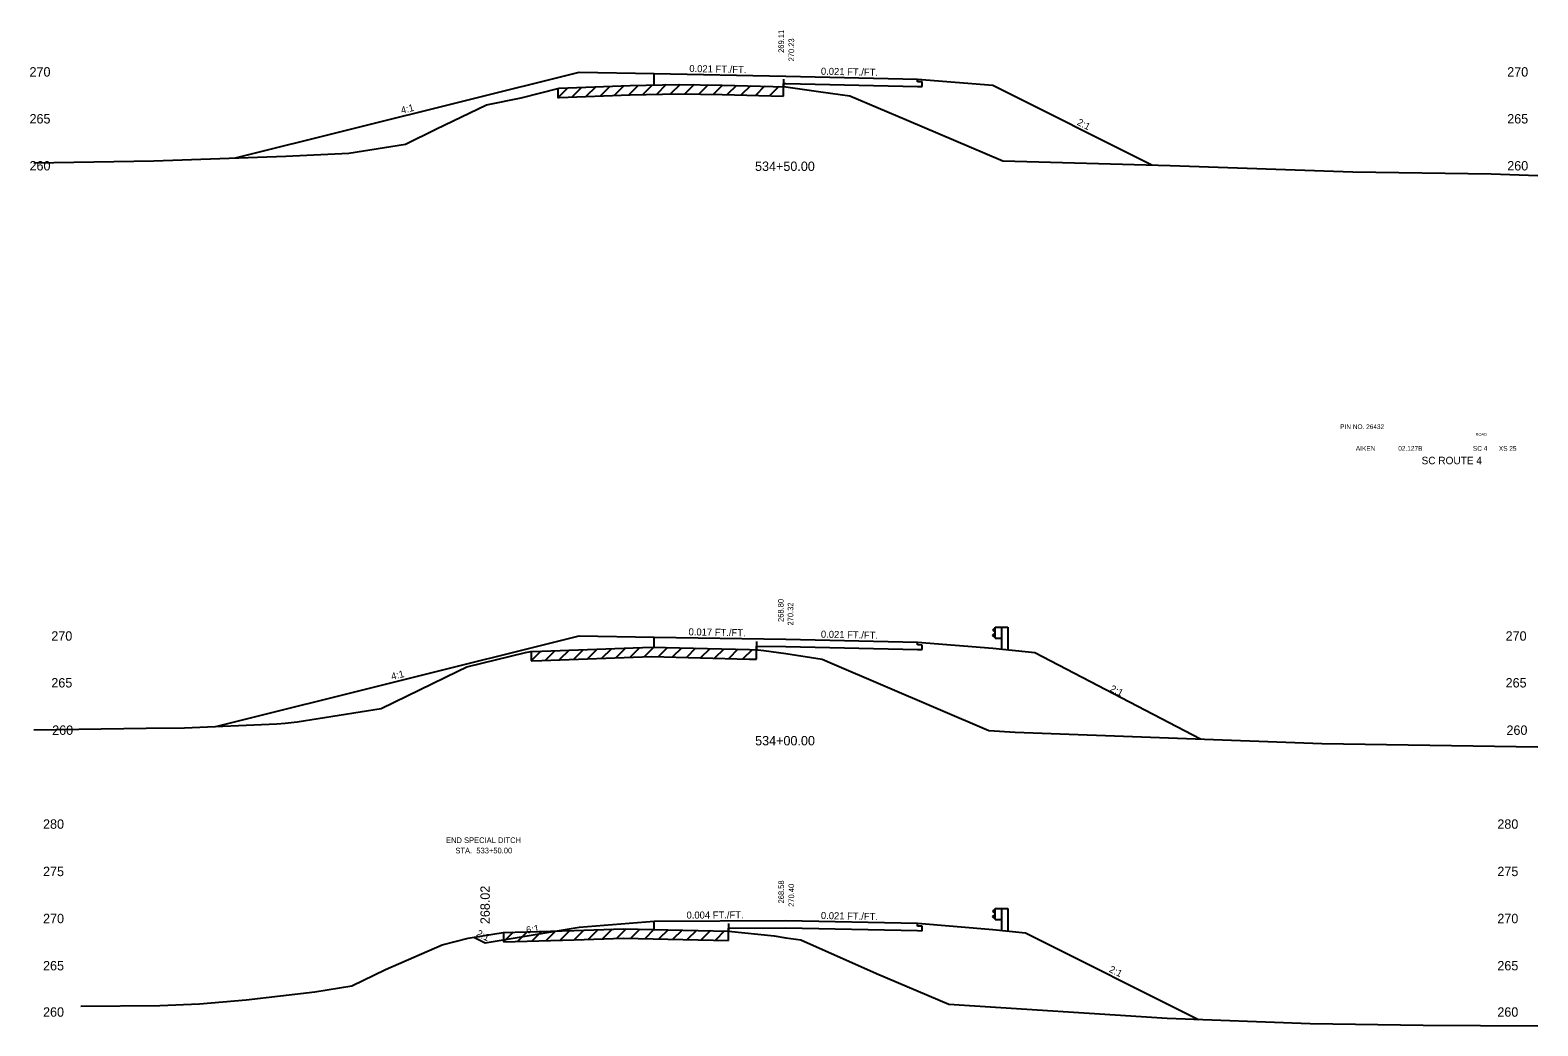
# Model space of a CAD drawing. Extents: x 883 to 1160, y 1002 to 4323.
# Drawn here: x 999.6 to 1160, y 3799.2 to 3905.1 of the extents above; entities that cross this region are included whole.
import ezdxf

# ---------------------------------------------------------------- set-up
doc = ezdxf.new("R2010")
doc.units = 0
for name, color, linetype in [('Level 1', 7, 'Continuous'), ('Level 10', 7, 'Continuous'), ('Level 11', 7, 'Continuous'), ('Level 12', 7, 'Continuous'), ('Level 24', 7, 'Continuous'), ('Level 3', 7, 'Continuous'), ('Level 32', 7, 'Continuous'), ('Level 33', 7, 'Continuous'), ('Level 53', 7, 'Continuous'), ('Level 59', 7, 'Continuous'), ('Level 6', 7, 'Continuous'), ('Level 60', 7, 'Continuous'), ('Level 61', 7, 'Continuous'), ('Level 7', 7, 'Continuous')]:
    doc.layers.add(name, color=color, linetype=linetype)

msp = doc.modelspace()

# ---------------------------------------------------------------- linework, layer by layer
at = {"layer": 'Level 11'}
for p, q in [((1066, 3899.3), (1066, 3900.52)), ((1094, 3899.64), (1094, 3899.94)), ((1094.5, 3899.63), (1094, 3899.64)), ((1094.5, 3899.15), (1094.5, 3899.63)), ((1094, 3899.16), (1094.5, 3899.15)), ((1066, 3839.47), (1066, 3840.57)), ((1094, 3839.73), (1094, 3840.03)), ((1094.5, 3839.72), (1094, 3839.73)), ((1094, 3839.25), (1094.5, 3839.24)), ((1094.5, 3839.24), (1094.5, 3839.72)), ((1066, 3809.45), (1066, 3810.35)), ((1094, 3809.81), (1094, 3810.11)), ((1094.5, 3809.8), (1094, 3809.81)), ((1094.5, 3809.32), (1094.5, 3809.8)), ((1094, 3809.33), (1094.5, 3809.32))]:
    msp.add_line(p, q, dxfattribs=at)
at = {"layer": 'Level 12'}
for p, q in [((1079.73, 3899.12), (1079.73, 3899.45)), ((1079.73, 3899.45), (1080, 3899.45)), ((1080, 3899.45), (1094, 3899.16)), ((1076.86, 3839.22), (1076.86, 3839.6)), ((1076.86, 3839.6), (1080, 3839.55)), ((1080, 3839.55), (1094, 3839.25)), ((1073.91, 3809.6), (1080, 3809.62)), ((1073.91, 3809.29), (1073.91, 3809.6)), ((1080, 3809.62), (1094, 3809.33))]:
    msp.add_line(p, q, dxfattribs=at)
at = {"layer": 'Level 24'}
for p, q in [((1102.27, 3840.45), (1102.27, 3841.62)), ((1102.27, 3841.62), (1102.94, 3841.62)), ((1102.94, 3841.62), (1102.94, 3839.27)), ((1102.94, 3841.62), (1103.6, 3841.62)), ((1103.6, 3841.62), (1103.6, 3839.21)), ((1102.27, 3841.54), (1102, 3841.34)), ((1102, 3841.34), (1102, 3841.29)), ((1102, 3841.29), (1102.27, 3841.09)), ((1102, 3840.77), (1102.27, 3840.97)), ((1102, 3840.72), (1102, 3840.77)), ((1102.27, 3840.52), (1102, 3840.72)), ((1102.27, 3840.45), (1102.94, 3840.45)), ((1102.27, 3811.62), (1102, 3811.42)), ((1102, 3811.42), (1102, 3811.37)), ((1102, 3811.37), (1102.27, 3811.17)), ((1102.27, 3810.53), (1102.27, 3811.69)), ((1102.27, 3811.69), (1102.94, 3811.69)), ((1102.94, 3811.69), (1102.94, 3809.35)), ((1102.94, 3811.69), (1103.6, 3811.69)), ((1103.6, 3811.69), (1103.6, 3809.28)), ((1102, 3810.85), (1102.27, 3811.05)), ((1102, 3810.8), (1102, 3810.85)), ((1102.27, 3810.6), (1102, 3810.8)), ((1102.27, 3810.53), (1102.94, 3810.53))]:
    msp.add_line(p, q, dxfattribs=at)
at = {"layer": 'Level 53'}
for p, q in [((1079.73, 3899.93), (1079.73, 3899.12)), ((1076.86, 3840.08), (1076.86, 3839.22)), ((1073.91, 3810.08), (1073.91, 3809.29))]:
    msp.add_line(p, q, dxfattribs=at)
at = {"layer": 'Level 59'}
for p, q in [((1066, 3900.52), (1080, 3900.23)), ((1080, 3900.23), (1094, 3899.94)), ((1066, 3840.57), (1080, 3840.33)), ((1080, 3840.33), (1094, 3840.03)), ((1066, 3810.35), (1080, 3810.4)), ((1080, 3810.4), (1094, 3810.11))]:
    msp.add_line(p, q, dxfattribs=at)
at = {"layer": 'Level 6'}
for p, q in [((1058, 3900.68), (1066, 3900.52)), ((1094, 3899.94), (1102, 3899.27)), ((1058, 3840.71), (1066, 3840.57)), ((1094, 3840.03), (1102, 3839.37)), ((1102, 3839.37), (1106.5, 3838.92)), ((1058, 3809.69), (1066, 3810.35)), ((1094, 3810.11), (1102, 3809.44)), ((1102, 3809.44), (1105.5, 3809.09))]:
    msp.add_line(p, q, dxfattribs=at)
at = {"layer": 'Level 60'}
for p, q in [((1063.42, 3899.24), (1068.59, 3899.37)), ((1068.59, 3899.37), (1073.21, 3899.3)), ((1048.14, 3897.21), (1051.82, 3897.95)), ((1051.82, 3897.95), (1055.88, 3898.96)), ((1055.88, 3898.96), (1063.42, 3899.24)), ((1073.21, 3899.3), (1080, 3899.11)), ((1080, 3899.11), (1083.71, 3898.57)), ((1083.71, 3898.57), (1086.8, 3898.15)), ((1086.8, 3898.15), (1092.82, 3895.61)), ((1042.77, 3894.59), (1048.14, 3897.21)), ((1039.54, 3893.01), (1042.77, 3894.59)), ((1092.82, 3895.61), (1103.09, 3891.22)), ((1033.51, 3892.05), (1039.54, 3893.01)), ((1012.74, 3891.22), (1026.81, 3891.74)), ((1026.81, 3891.74), (1033.51, 3892.05)), ((1000, 3891.03), (1012.74, 3891.22)), ((1103.09, 3891.22), (1120.87, 3890.75)), ((1120.87, 3890.75), (1140.33, 3890.05)), ((1140.33, 3890.05), (1155.03, 3889.84)), ((1155.03, 3889.84), (1160, 3889.69)), ((1046.07, 3837.38), (1052.3, 3838.94)), ((1052.3, 3838.94), (1052.87, 3839.03)), ((1052.87, 3839.03), (1054.03, 3839.06)), ((1054.03, 3839.06), (1065.69, 3839.48)), ((1065.69, 3839.48), (1076.14, 3839.23)), ((1076.14, 3839.23), (1077.01, 3839.21)), ((1077.01, 3839.21), (1077.66, 3839.14)), ((1077.66, 3839.14), (1080, 3838.8)), ((1080, 3838.8), (1083.86, 3838.23)), ((1036.96, 3832.98), (1045.11, 3836.95)), ((1045.11, 3836.95), (1046.07, 3837.38)), ((1083.86, 3838.23), (1084.91, 3837.76)), ((1084.91, 3837.76), (1101.6, 3830.63)), ((1028, 3831.56), (1036.96, 3832.98)), ((1000, 3830.71), (1011.95, 3830.87)), ((1011.95, 3830.87), (1016.03, 3830.89)), ((1016.03, 3830.89), (1025.86, 3831.33)), ((1025.86, 3831.33), (1026.73, 3831.41)), ((1026.73, 3831.41), (1028, 3831.56)), ((1101.6, 3830.63), (1104.38, 3830.45)), ((1104.38, 3830.45), (1137.02, 3829.23)), ((1137.02, 3829.23), (1160, 3828.89)), ((1057.46, 3809.34), (1062.72, 3809.53)), ((1062.72, 3809.53), (1067.44, 3809.42)), ((1043.44, 3807.83), (1046.2, 3808.53)), ((1046.2, 3808.53), (1049.94, 3809.12)), ((1049.94, 3809.12), (1057.46, 3809.34)), ((1067.44, 3809.42), (1073.89, 3809.29)), ((1073.89, 3809.29), (1078.77, 3808.76)), ((1078.77, 3808.76), (1080, 3808.58)), ((1080, 3808.58), (1081.6, 3808.34)), ((1081.6, 3808.34), (1089.65, 3804.78)), ((1037.4, 3805.18), (1043.44, 3807.83)), ((1033.82, 3803.44), (1037.4, 3805.18)), ((1089.65, 3804.78), (1097.33, 3801.5)), ((1029.9, 3802.82), (1033.82, 3803.44)), ((1013.41, 3801.35), (1017.62, 3801.54)), ((1017.62, 3801.54), (1022.58, 3801.97)), ((1022.58, 3801.97), (1029.9, 3802.82)), ((1097.33, 3801.5), (1120.55, 3800.02)), ((1005, 3801.31), (1013.41, 3801.35)), ((1120.55, 3800.02), (1135.77, 3799.45)), ((1135.77, 3799.45), (1147.79, 3799.27)), ((1147.79, 3799.27), (1160, 3799.2))]:
    msp.add_line(p, q, dxfattribs=at)
at = {"layer": 'Level 61'}
for p, q in [((1068.77, 3899.37), (1067.74, 3898.35)), ((1070.23, 3899.35), (1069.25, 3898.36)), ((1056.8, 3899), (1055.73, 3897.93)), ((1055.73, 3898.93), (1055.73, 3897.93)), ((1055.73, 3897.93), (1055.88, 3897.96)), ((1055.88, 3897.96), (1063.42, 3898.24)), ((1058.27, 3899.05), (1057.23, 3898.01)), ((1059.77, 3899.1), (1058.73, 3898.07)), ((1061.27, 3899.16), (1060.23, 3898.12)), ((1062.77, 3899.21), (1061.74, 3898.18)), ((1064.27, 3899.26), (1063.24, 3898.23)), ((1063.42, 3898.24), (1068.59, 3898.37)), ((1065.77, 3899.3), (1064.74, 3898.27)), ((1067.27, 3899.34), (1066.24, 3898.31)), ((1068.59, 3898.37), (1073.21, 3898.3)), ((1071.73, 3899.32), (1070.75, 3898.34)), ((1073.24, 3899.29), (1072.25, 3898.31)), ((1073.21, 3898.3), (1079.73, 3898.12)), ((1074.73, 3899.25), (1073.75, 3898.28)), ((1076.23, 3899.21), (1075.26, 3898.24)), ((1077.73, 3899.17), (1076.76, 3898.2)), ((1079.24, 3899.13), (1078.26, 3898.16)), ((1079.73, 3898.12), (1079.73, 3899.12)), ((1053.92, 3839.06), (1052.89, 3838.03)), ((1052.89, 3839.03), (1052.89, 3838.03)), ((1054.03, 3838.06), (1065.69, 3838.48)), ((1055.43, 3839.11), (1054.39, 3838.07)), ((1056.93, 3839.16), (1055.89, 3838.13)), ((1058.43, 3839.22), (1057.4, 3838.18)), ((1059.94, 3839.27), (1058.9, 3838.24)), ((1061.44, 3839.33), (1060.4, 3838.29)), ((1062.94, 3839.38), (1061.9, 3838.34)), ((1064.44, 3839.43), (1063.41, 3838.4)), ((1065.93, 3839.47), (1064.91, 3838.45)), ((1065.69, 3838.48), (1076.14, 3838.23)), ((1067.39, 3839.44), (1066.41, 3838.46)), ((1068.89, 3839.4), (1067.91, 3838.43)), ((1070.39, 3839.37), (1069.42, 3838.39)), ((1071.9, 3839.33), (1070.92, 3838.35)), ((1073.4, 3839.29), (1072.42, 3838.32)), ((1074.9, 3839.26), (1073.92, 3838.28)), ((1076.41, 3839.22), (1075.43, 3838.25)), ((1076.86, 3838.22), (1076.86, 3839.22)), ((1052.89, 3838.03), (1054.03, 3838.06)), ((1076.14, 3838.23), (1076.86, 3838.22)), ((1063, 3809.52), (1061.98, 3808.5)), ((1050.99, 3809.15), (1049.96, 3808.12)), ((1049.96, 3809.12), (1049.96, 3808.12)), ((1049.96, 3808.12), (1057.46, 3808.34)), ((1052.49, 3809.2), (1051.46, 3808.17)), ((1054, 3809.24), (1052.96, 3808.21)), ((1055.5, 3809.28), (1054.47, 3808.25)), ((1057, 3809.33), (1055.97, 3808.3)), ((1057.46, 3808.34), (1062.72, 3808.53)), ((1058.51, 3809.38), (1057.47, 3808.34)), ((1060.01, 3809.43), (1058.97, 3808.39)), ((1061.52, 3809.49), (1060.48, 3808.45)), ((1062.72, 3808.53), (1067.44, 3808.42)), ((1064.46, 3809.49), (1063.48, 3808.51)), ((1065.96, 3809.45), (1064.98, 3808.47)), ((1067.47, 3809.42), (1066.49, 3808.44)), ((1067.44, 3808.42), (1073.89, 3808.29)), ((1068.97, 3809.39), (1067.99, 3808.41)), ((1070.48, 3809.36), (1069.49, 3808.38)), ((1071.98, 3809.33), (1070.99, 3808.35)), ((1073.48, 3809.3), (1072.5, 3808.32)), ((1073.89, 3808.29), (1073.91, 3808.29)), ((1073.91, 3808.29), (1073.91, 3809.29))]:
    msp.add_line(p, q, dxfattribs=at)
at = {"layer": 'Level 7'}
for p, q in [((1021.43, 3891.54), (1058, 3900.68)), ((1102, 3899.27), (1118.93, 3890.81)), ((1019.35, 3831.04), (1058, 3840.71)), ((1106.5, 3838.92), (1124.1, 3829.72)), ((1048, 3808.02), (1058, 3809.69)), ((1046.8, 3808.62), (1048, 3808.02)), ((1105.5, 3809.09), (1123.9, 3799.89))]:
    msp.add_line(p, q, dxfattribs=at)

# ---------------------------------------------------------------- texts
at = {"layer": 'Level 1'}
for s, height, p in [('534+50.00', 1, (1076.72, 3890.16)), ('PIN NO. 26432', 0.5, (1138.97, 3862.7)), ('AIKEN', 0.5, (1140.64, 3860.39)), ('02.127B', 0.5, (1145.15, 3860.39)), ('SC 4', 0.5, (1153.09, 3860.39)), ('XS 25', 0.5, (1155.85, 3860.39)), ('SC ROUTE 4', 0.8, (1147.63, 3858.95)), ('534+00.00', 1, (1076.73, 3829.04))]:
    msp.add_text(s, height=height, dxfattribs=at).set_placement(p)
at = {"layer": 'Level 10'}
for s, p in [('269.11', (1079.8, 3902.72)), ('268.80', (1079.76, 3842.17)), ('268.58', (1079.8, 3812.22))]:
    msp.add_text(s, height=0.6, rotation=90, dxfattribs=at).set_placement(p)
at = {"layer": 'Level 3'}
for s, height, p in [(' 270', 1, (999.16, 3900.2)), (' 270', 1, (1156.37, 3900.2)), (' 265', 1, (999.16, 3895.21)), (' 265', 1, (1156.37, 3895.21)), (' 260', 1, (999.16, 3890.21)), (' 260', 1, (1156.37, 3890.21)), ('ROAD', 0.3, (1153.38, 3861.98)), (' 270', 1, (1001.48, 3840.18)), (' 270', 1, (1156.2, 3840.18)), (' 265', 1, (1001.48, 3835.2)), (' 265', 1, (1156.2, 3835.2)), (' 260', 1, (1001.57, 3830.16)), (' 260', 1, (1156.29, 3830.16)), (' 280', 1, (1000.6, 3820.17)), (' 280', 1, (1155.32, 3820.17)), (' 275', 1, (1000.6, 3815.13)), (' 275', 1, (1155.32, 3815.13)), (' 270', 1, (1000.6, 3810.12)), (' 270', 1, (1155.32, 3810.12)), (' 265', 1, (1000.6, 3805.1)), (' 265', 1, (1155.32, 3805.1)), (' 260', 1, (1000.6, 3800.17)), (' 260', 1, (1155.32, 3800.17))]:
    msp.add_text(s, height=height, dxfattribs=at).set_placement(p)
at = {"layer": 'Level 32'}
for s, rotation, p in [('0.021 FT./FT.', 358.8084, (1069.72, 3900.69)), ('0.021 FT./FT.', 358.8084, (1083.72, 3900.4)), ('4:1', 14.0362, (1039.14, 3896.23)), ('2:1', 333.435, (1110.91, 3895.1)), ('0.017 FT./FT.', 359.0092, (1069.64, 3840.75)), ('0.021 FT./FT.', 358.8084, (1083.72, 3840.5)), ('4:1', 14.0362, (1038.1, 3835.99)), ('2:1', 333.435, (1114.41, 3834.84)), ('0.004 FT./FT.', 0.2009, (1069.43, 3810.61)), ('0.021 FT./FT.', 358.8084, (1083.72, 3810.57)), ('6:1', 9.4623, (1052.43, 3809.01)), ('2:1', 333.435, (1047, 3808.8)), ('2:1', 333.435, (1114.31, 3804.97))]:
    msp.add_text(s, height=0.75, rotation=rotation, dxfattribs=at).set_placement(p)
for s, p in [('END SPECIAL DITCH', (1043.84, 3818.65)), ('STA.  533+50.00', (1044.84, 3817.55))]:
    msp.add_text(s, height=0.6, dxfattribs=at).set_placement(p)
at = {"layer": 'Level 33'}
msp.add_text('268.02', height=1, rotation=90, dxfattribs=at).set_placement((1048.5, 3810.02))
at = {"layer": 'Level 59'}
for s, p in [(' 270.23', (1080.88, 3901.59)), (' 270.32', (1080.79, 3841.57)), (' 270.40', (1080.88, 3811.64))]:
    msp.add_text(s, height=0.6, rotation=90, dxfattribs=at).set_placement(p)

doc.saveas('drawing.dxf')
